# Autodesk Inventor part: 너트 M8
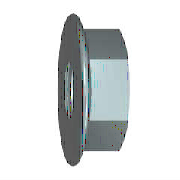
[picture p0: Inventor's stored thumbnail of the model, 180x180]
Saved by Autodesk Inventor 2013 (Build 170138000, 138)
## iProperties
Created: 2015-09
Part Number: 너트 M8
Material: 스테인리스강
Description: 플랜지붙이 6각 너트 - 일반 스레드
Document SubType Name: Modeling
Standard: ISO 4161
Designer: mduedu
Standard Revision: 2판 1999-03-15
Standards Organization: ISO
Language: ko-KR
Size Designation: M8
Categories: <MemberInstance><Categories><Category DisplayName="조임쇠" InternalName="e4da775c-781d-43d5-af7c-5136215cf5a6" Mnemonic="FSTN"><Category DisplayName="너트" InternalN
Density: 8.08 g/cm^3
Author: mduedu
IsCustomPart: 1
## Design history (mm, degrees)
sketch "스케치1"
  geometry: L1 (-1.844, 0)-(9.641, 0) reference; L2 (3.107, 6.5)-(2.288, 8.257); L3 (3.107, 6.5)-(8, 6.5); L4 (8, 6.5)-(8, 0); L5 (3.107, 6.5)-(3.107, 0); L6 (0, -1.835)-(0, 11.01) reference; A1 r 1.2 centre (1.2, 7.75) between (2.288, 8.257) and (0, 7.75); 1 further point
  constraints: 8 end point, 3 point on line, 2 perpendicular, 2 point on circle, 2 tangent, 1 centre point, 1 parallel
  dimensions: "d2" = 13 diameter of L3 L1 (= SW); "d4" = 17.9 dimension on A1 L1 (= LADI); "d5" = 1.2 radius of A1 (= PHH); "d15" = 8 distance between parallel lines of L4 L6 (= KOH); "d16" = 25 deg angle of L6 L2 (= KEWI)
revolve "링" sketch "스케치1" stored, may be unused: angle "d8" = 90 deg
sketch "스케치2"
  geometry: L1 (-6.5, -3.753)-(-6.5, 3.753); L2 (-6.5, 3.753)-(0, 7.506); L3 (0, 7.506)-(6.5, 3.753); L4 (6.5, 3.753)-(6.5, -3.753); L5 (6.5, -3.753)-(0, -7.506); L6 (0, -7.506)-(-6.5, -3.753); C1 r 4.9 at (0, 0); C2 r 7.75 at (0, 0) reference; 1 further point
  constraints: 12 end point, 1 centre point, 1 coincident, 1 vertical, 11 other
  dimensions: "d6" = 15.01111 distance of L5.end L2.end (= 1.1547 x SW)
extrude "본체" join sketch "스케치2" distance "d7" = 8 (= KOH); taper "d9" = 0 deg
sketch "스케치3"
  geometry: L1 (2.638, 7.506)-(8, 7.506) reference; L2 (8, 3.753)-(8, 7.506) reference; L3 (0, -7.75)-(0, 7.75) reference; L4 (-1.6, 0)-(9.6, 0) reference; L5 (7.419, 7.506)-(8, 6.5)
  constraints: 2 end point, 2 point on line
  dimensions: "d10" = 30 deg angle of L2 L5 (= ANG1); "d11" = 13 diameter of L5.end L4 (= SW0)
revolve "모따기1" sketch "스케치3" stored, may be unused: angle "d24" = 90 deg
sketch "스케치4"
  geometry: C1 r 7.75 at (0, 0) reference; 1 further point
  constraints: 1 coincident
hole "스레드" sketch "스케치4" at (0, 0) diameter "d25" = 6.647; stored, may be unused: countersink angle "d29" = 82 deg, drill point angle "d31" = 118 deg; dims "d26" = 6, "d27" = 4, "d28" = 2, "d30" = 8
workaxis "Work Axis1"
workplane "Work Plane1"
body "Solid1"
chamfer "모따기2" distance "d12" = 0.67658 (= -0.5 x GD1 + 0.5 x NND); stored, may be unused: angle "d13" = 30 deg, second distance "d46" = 0.67658 (= -0.5 x GD1 + 0.5 x NND)
chamfer "모따기3" distance "d51" = 0.67658 (= -0.5 x GD1 + 0.5 x NND); stored, may be unused: second distance "d52" = 2, angle "d53" = 45 deg
other parameters: "ANG1" = 30 deg [user parameter; used in 1 equation term], "KEWI" = 25 deg [user parameter; used in 1 equation term], "NND" = 8 [user parameter; used in 4 equation terms], "LADI" = 17.9 [user parameter; used in 2 equation terms], "SW" = 13 [user parameter; used in 3 equation terms], "PHH" = 1.2 [user parameter; used in 3 equation terms], "KOH" = 8 (= NND) [user parameter; used in 2 equation terms], "SW0" = 13 [user parameter; used in 1 equation term], "GD1" = 6.64684 (computed from THREADDIA, PTC, TOA) [user parameter; used in 3 equation terms], "d1" = 17.9 (= LADI), "d3" = 1.2 (= PHH), "d45" = 0, "d47" = 0, "d49" = 0, "d54" = 0, "GUL" = 0.67658 (= 0.541266 x PTC) [user parameter], "TPU" = 8 (computed from PTC) [user parameter], "RR" = 1.2 (= PHH) [user parameter], "THREADDIA" = 8 [user parameter; used in 1 equation term], "TOA" = 30 deg [user parameter; used in 1 equation term], "PTC" = 1.25 [user parameter; used in 4 equation terms], "GAL" = 0.67658 (= 0.541266 x PTC) [user parameter], "E0" = 15.015 (= 1.155 x SW) [user parameter]
